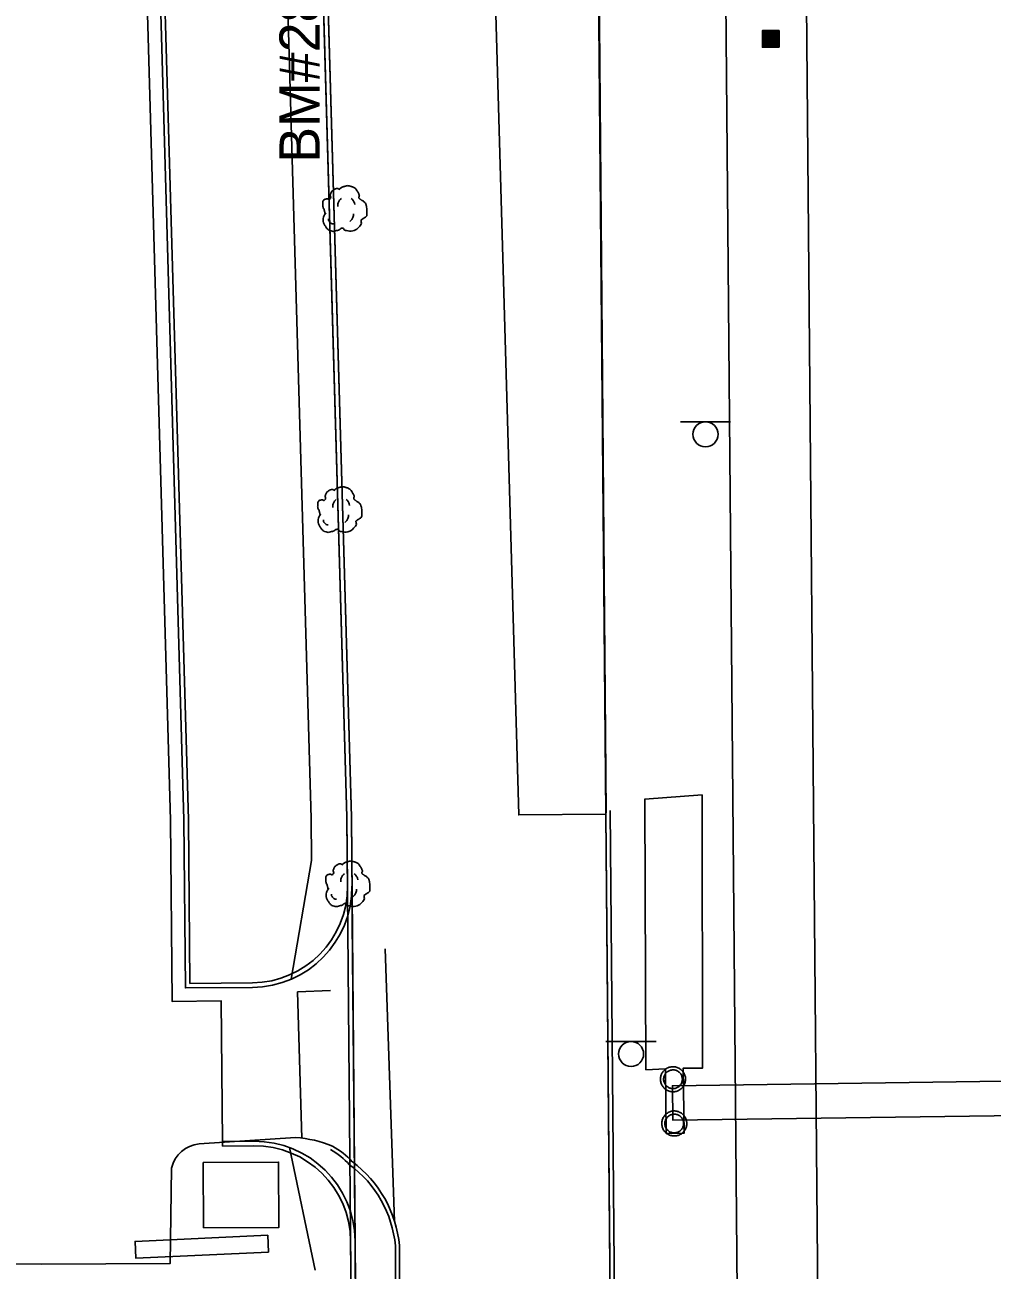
# Model space of a CAD drawing. Extents: x 2145380 to 2157287, y 139568 to 149130.
# Drawn here: x 2150661.9 to 2150806.3, y 141333.7 to 141519.7 of the extents above; entities that cross this region are included whole.
import ezdxf

# ---------------------------------------------------------------- set-up
doc = ezdxf.new("R2010")
doc.units = 0
for name, color, linetype in [('PR_PREVIOUSLY CONSTRUCTED', 7, 'Continuous'), ('SURV_Benchmark', 7, 'Continuous'), ('TOPO_Asphalt', 7, 'Continuous'), ('TOPO_Concrete', 7, 'Continuous'), ('TOPO_Curb Back', 7, 'Continuous'), ('TOPO_Misc', 7, 'Continuous'), ('TOPO_Power Pole', 7, 'Continuous'), ('TOPO_Sign', 7, 'Continuous'), ('TOPO_Tree', 7, 'Continuous'), ('TOPO_Wall Freestanding', 7, 'Continuous')]:
    doc.layers.add(name, color=color, linetype=linetype)

# ---------------------------------------------------------------- blocks, each defined once
blk = doc.blocks.new('CB')
at = {"layer": 'TOPO_Misc'}
for p, q in [((-3.08, 2.99), (3.24, 2.99)), ((-3.08, 2.68), (3.24, 2.68)), ((-3.08, 2.36), (3.24, 2.36)), ((-3.08, 2.05), (3.24, 2.05)), ((-3.08, 1.73), (3.24, 1.73)), ((-3.08, 1.4), (3.24, 1.4)), ((-3.08, 1.1), (3.24, 1.1)), ((-3.08, 0.77), (3.24, 0.77)), ((-3.08, 0.46), (3.24, 0.46)), ((-3.08, 0.14), (3.24, 0.14)), ((-3.08, -0.17), (3.24, -0.17)), ((-3.08, -0.48), (3.24, -0.48)), ((-3.08, -0.8), (3.24, -0.8)), ((-3.08, -1.11), (3.26, -1.11)), ((-3.08, -1.43), (3.26, -1.43)), ((-3.08, -1.75), (3.26, -1.75)), ((-3.08, -2.07), (3.26, -2.07)), ((-3.08, -2.39), (3.26, -2.39)), ((-3.08, -2.7), (3.26, -2.7)), ((-3.08, -3.02), (3.26, -3.02))]:
    blk.add_line(p, q, dxfattribs=at)
blk.add_lwpolyline([(3.26, -3.29), (3.24, 3.05), (-3.09, 3.04), (-3.08, -3.3), (3.26, -3.29)], dxfattribs=at)
blk = doc.blocks.new('TREE')
at = {"layer": 'TOPO_Tree'}
for points in [[(-3.49, 17.6), (-3.07, 18.27), (-2.58, 18.8), (-1.9, 19.19), (-1.05, 19.68), (-0.19, 19.96), (0.74, 20.24), (1.62, 20.51), (2.51, 20.82), (3.39, 20.77), (4.1, 20.73), (4.8, 20.47), (5.51, 20.24), (6.43, 19.95), (7.32, 19.73), (8.15, 19.19), (9.36, 18.4), (10.02, 17.21), (10.8, 16.01), (11.24, 15.33), (11.58, 14.62), (11.86, 13.89), (12.17, 13.08), (11.37, 12.02), (11.86, 11.25), (12, 11.03), (12.18, 10.86), (12.39, 10.72), (12.91, 10.35), (13.45, 10.02), (13.97, 9.66), (14.7, 9.16), (15.41, 8.68), (16.09, 8.07), (16.7, 7.53), (16.93, 6.73), (17.15, 5.95), (17.59, 4.38), (17.71, 2.77), (17.68, 1.19), (17.65, -0.25), (17.83, -2.22), (16.62, -3.04), (15.47, -3.83), (14.31, -4.58), (13.16, -5.35)], [(-14.07, -0.4), (-14.17, 0.5), (-14.37, 1.38), (-14.6, 2.25), (-14.84, 3.17), (-15.47, 3.96), (-15.66, 4.9), (-15.8, 5.59), (-15.71, 6.31), (-15.66, 7.01), (-15.6, 7.91), (-15.72, 8.8), (-15.13, 9.66), (-14.62, 10.42), (-13.76, 10.49), (-13.02, 10.72), (-12.18, 10.98), (-11.06, 10), (-10.37, 10.72), (-9.4, 11.74), (-10.29, 13.28), (-9.84, 14.42), (-9.56, 15.15), (-9.32, 15.89), (-8.78, 16.54), (-8.18, 17.26), (-7.5, 17.68), (-6.67, 18.13), (-6.14, 18.41), (-5.61, 18.61), (-5.08, 18.66), (-4.55, 18.71), (-4.02, 18.54), (-3.49, 18.13)], [(-4.21, 5.09), (-4.46, 6.09), (-4.3, 7.21), (-3.84, 8.21), (-3.33, 9.34), (-2.71, 10.27), (-1.64, 10.97)], [(5.89, 11.15), (6.5, 10.68), (6.96, 10.17), (7.36, 9.5), (7.93, 8.56), (8.31, 7.6), (8.46, 6.56)], [(13.16, -5.34), (13.25, -5.81), (13.36, -6.28), (13.45, -6.75), (13.76, -8.52), (12.24, -10.03), (10.8, -11.51), (9.98, -12.34), (9.13, -12.77), (8.15, -13.1), (5.97, -13.83), (3.32, -13.56), (1.27, -13.1), (0.49, -12.92), (-0.06, -11.44), (-0.84, -11.51), (-2.04, -11.61), (-3.28, -12.78), (-4.55, -13.1), (-6.06, -13.47), (-7.77, -14.03), (-9.31, -13.62), (-11.36, -13.09), (-12.84, -11.41), (-14.07, -9.39), (-15.32, -7.35), (-15.61, -5.13), (-15.13, -3.04), (-14.87, -1.89), (-13.91, -0.75), (-13.54, 0.13)], [(-11.38, -4.46), (-11.47, -5.41), (-11.03, -6.32), (-10.09, -7.22), (-9.3, -7.97), (-8.49, -8.26), (-7.7, -8.14)], [(4.79, -6.29), (5.71, -5.66), (6.3, -4.92), (6.81, -3.91), (7.36, -2.81), (7.63, -1.7), (7.54, -0.6)]]:
    blk.add_open_spline(points, degree=3, dxfattribs=at)

msp = doc.modelspace()

# ---------------------------------------------------------------- linework, layer by layer
at = {"layer": 'PR_PREVIOUSLY CONSTRUCTED'}
for p, q in [((2150710.64, 141401.31), (2150701.75, 141710.59)), ((2150704.64, 141401.14), (2150698.44, 141616.88)), ((2150709.98, 141401.3), (2150703.73, 141618.37)), ((2150704.7, 141394.85), (2150704.64, 141401.26)), ((2150710.06, 141391.02), (2150709.97, 141401.31)), ((2150712.62, 141175.71), (2150710.64, 141401.31)), ((2150750.61, 141176.04), (2150748.64, 141401.78)), ((2150701.67, 141377.12), (2150704.7, 141394.85)), ((2150685.86, 141375.81), (2150695.86, 141375.9)), ((2150686.52, 141376.48), (2150695.86, 141376.57)), ((2150683.88, 141373.79), (2150691.21, 141373.86)), ((2150691.4, 141352.86), (2150691.21, 141373.86)), ((2150691.4, 141352.86), (2150696.06, 141352.9)), ((2150691.4, 141352.86), (2150691.4, 141352.19)), ((2150691.4, 141352.19), (2150696.07, 141352.23)), ((2150701.41, 141351.97), (2150705.23, 141333.67)), ((2150711.09, 141273.77), (2150710.53, 141338.03))]:
    msp.add_line(p, q, dxfattribs=at)
for points in [[(2150764.84, 141722.12), (2150774.08, 140666.28)], [(2150776.84, 141722.22), (2150788.7, 140366.39)], [(2150746.27, 141672.29), (2150748.64, 141401.78)], [(2150680.41, 141606.01), (2150682.95, 141517.92), (2150686.31, 141400.93), (2150686.52, 141376.48)], [(2150679.77, 141605.33), (2150682.28, 141517.9), (2150685.64, 141400.92), (2150685.86, 141375.81)], [(2150677.82, 141603.31), (2150680.28, 141517.84), (2150683.64, 141400.88), (2150683.88, 141373.79)]]:
    msp.add_lwpolyline(points, dxfattribs=at)
for centre, radius, start, end in [((2150695.73, 141390.9), 15, 270.5015, 0.5015), ((2150695.73, 141390.9), 14.33, 270.5015, 0.5015), ((2150696.2, 141337.9), 15, 0.5015, 90.5015), ((2150696.2, 141337.9), 14.33, 0.5015, 90.5015)]:
    msp.add_arc(centre, radius, start, end, dxfattribs=at)
at = {"layer": 'TOPO_Asphalt'}
for p, q in [((2150717.09, 141340.93), (2150715.71, 141381.66)), ((2150707.51, 141375.44), (2150702.61, 141375.22)), ((2150703.25, 141353.37), (2150702.61, 141375.22))]:
    msp.add_line(p, q, dxfattribs=at)
for points in [[(2150687.92, 141352.52), (2150702.31, 141353.46)], [(2150507.36, 141335.36), (2150559.92, 141335.75), (2150664.35, 141334.54), (2150683.58, 141334.64), (2150683.79, 141348.9)]]:
    msp.add_lwpolyline(points, dxfattribs=at)
for centre, radius, start, end in [((2150701.16, 141335.83), 17.67, 67.7958, 86.2585), ((2150688.37, 141347.83), 4.71, 95.5163, 166.8365)]:
    msp.add_arc(centre, radius, start, end, dxfattribs=at)
at = {"layer": 'TOPO_Concrete'}
for points in [[(2150748.68, 141401.99), (2150746.33, 141679), (2150745.89, 141700.43)], [(2150645.26, 141604.93), (2150641.05, 141604.88), (2150641.07, 141602.89), (2150677.82, 141603.29), (2150680.28, 141517.84), (2150683.64, 141400.88), (2150683.88, 141373.79), (2150691.21, 141373.86), (2150691.4, 141352.86), (2150696.06, 141352.9)], [(2150695.86, 141375.9), (2150685.86, 141375.81), (2150685.64, 141400.92), (2150682.28, 141517.9), (2150679.77, 141605.32), (2150668.62, 141605.19)], [(2150754.48, 141404.03), (2150763.01, 141404.65), (2150763.06, 141363.82), (2150760.18, 141363.81), (2150760.32, 141354.11), (2150757.64, 141354.08), (2150757.54, 141363.74), (2150754.62, 141363.57)], [(2150711.2, 141338.03), (2150710.73, 141391.03)]]:
    msp.add_lwpolyline(points, dxfattribs=at)
for centre, start, end in [((2150695.73, 141390.9), 270.5015, 0.5015), ((2150696.2, 141337.9), 0.5015, 90.5015)]:
    msp.add_arc(centre, 15, start, end, dxfattribs=at)
at = {"layer": 'TOPO_Curb Back'}
for points in [[(2150712.62, 141175.71), (2150710.64, 141401.31), (2150701.75, 141710.59)], [(2150729.16, 141661.71), (2150728.16, 141661.69), (2150735.64, 141401.66), (2150748.64, 141401.78), (2150750.61, 141176.04)], [(2150711.95, 141175.71), (2150709.97, 141401.3), (2150703.7, 141619.51)], [(2150749.3, 141402.29), (2150751.28, 141176.05)], [(2150717.73, 141271.44), (2150717.35, 141302.24), (2150717.21, 141337.29)], [(2150718.33, 141271.46), (2150717.95, 141302.24), (2150717.81, 141337.32)]]:
    msp.add_lwpolyline(points, dxfattribs=at)
for centre, radius, start, end in [((2150701.61, 141341.33), 11.92, 42.624, 60.1597), ((2150701.61, 141341.33), 12.52, 42.8876, 60.1591), ((2150700.24, 141335.7), 17.05, 5.3752, 53.4905), ((2150700.24, 141335.7), 17.65, 5.2866, 53.3058)]:
    msp.add_arc(centre, radius, start, end, dxfattribs=at)
at = {"layer": 'TOPO_Power Pole'}
for points in [[(2150756.79, 141362.17), (2150756.8, 141362.3), (2150756.81, 141362.43), (2150756.83, 141362.56), (2150756.87, 141362.69), (2150756.91, 141362.82), (2150756.96, 141362.94), (2150757.02, 141363.06), (2150757.08, 141363.18), (2150757.17, 141363.28), (2150757.24, 141363.39), (2150757.33, 141363.48), (2150757.43, 141363.58), (2150757.53, 141363.66), (2150757.64, 141363.74), (2150757.76, 141363.81), (2150757.88, 141363.86), (2150757.99, 141363.92), (2150758.12, 141363.96), (2150758.25, 141364), (2150758.38, 141364.02), (2150758.51, 141364.04), (2150758.64, 141364.04), (2150758.77, 141364.04), (2150758.9, 141364.03), (2150759.03, 141364.01), (2150759.16, 141363.98), (2150759.29, 141363.94), (2150759.41, 141363.88), (2150759.53, 141363.83), (2150759.65, 141363.77), (2150759.76, 141363.7), (2150759.86, 141363.62), (2150759.96, 141363.53), (2150760.05, 141363.43), (2150760.14, 141363.33), (2150760.21, 141363.22), (2150760.28, 141363.11), (2150760.35, 141362.99), (2150760.4, 141362.87), (2150760.45, 141362.74), (2150760.48, 141362.62), (2150760.51, 141362.49), (2150760.53, 141362.36), (2150760.53, 141362.22), (2150760.53, 141362.1), (2150760.53, 141361.97), (2150760.5, 141361.83), (2150760.48, 141361.7), (2150760.44, 141361.58), (2150760.39, 141361.45), (2150760.33, 141361.34), (2150760.28, 141361.22), (2150760.2, 141361.11), (2150760.12, 141361), (2150760.03, 141360.9), (2150759.94, 141360.8), (2150759.84, 141360.72), (2150759.73, 141360.64), (2150759.63, 141360.57), (2150759.51, 141360.5), (2150759.39, 141360.45), (2150759.27, 141360.4), (2150759.13, 141360.36), (2150759.01, 141360.33), (2150758.88, 141360.31), (2150758.75, 141360.3), (2150758.62, 141360.3), (2150758.49, 141360.31), (2150758.36, 141360.33), (2150758.23, 141360.36), (2150758.1, 141360.39), (2150757.98, 141360.44), (2150757.85, 141360.49), (2150757.73, 141360.55), (2150757.63, 141360.62), (2150757.52, 141360.7), (2150757.41, 141360.78), (2150757.32, 141360.88), (2150757.23, 141360.97), (2150757.15, 141361.08), (2150757.08, 141361.19), (2150757.01, 141361.3), (2150756.95, 141361.43), (2150756.9, 141361.55), (2150756.86, 141361.68), (2150756.83, 141361.8), (2150756.81, 141361.93), (2150756.8, 141362.06), (2150756.79, 141362.17)], [(2150757.26, 141362.17), (2150757.27, 141362.28), (2150757.28, 141362.4), (2150757.3, 141362.51), (2150757.34, 141362.62), (2150757.38, 141362.73), (2150757.43, 141362.83), (2150757.49, 141362.93), (2150757.55, 141363.02), (2150757.63, 141363.11), (2150757.71, 141363.19), (2150757.79, 141363.27), (2150757.89, 141363.34), (2150757.98, 141363.39), (2150758.09, 141363.45), (2150758.19, 141363.49), (2150758.3, 141363.53), (2150758.42, 141363.55), (2150758.53, 141363.57), (2150758.64, 141363.57), (2150758.75, 141363.57), (2150758.86, 141363.56), (2150758.98, 141363.54), (2150759.09, 141363.51), (2150759.19, 141363.47), (2150759.3, 141363.43), (2150759.4, 141363.37), (2150759.49, 141363.3), (2150759.59, 141363.23), (2150759.67, 141363.15), (2150759.74, 141363.07), (2150759.82, 141362.97), (2150759.88, 141362.88), (2150759.93, 141362.77), (2150759.98, 141362.67), (2150760.01, 141362.56), (2150760.04, 141362.45), (2150760.06, 141362.33), (2150760.07, 141362.22), (2150760.07, 141362.11), (2150760.06, 141362), (2150760.03, 141361.89), (2150760.01, 141361.78), (2150759.97, 141361.67), (2150759.93, 141361.56), (2150759.88, 141361.46), (2150759.81, 141361.37), (2150759.74, 141361.27), (2150759.66, 141361.19), (2150759.58, 141361.11), (2150759.49, 141361.04), (2150759.39, 141360.98), (2150759.3, 141360.92), (2150759.18, 141360.87), (2150759.08, 141360.83), (2150758.97, 141360.8), (2150758.86, 141360.78), (2150758.74, 141360.77), (2150758.64, 141360.77), (2150758.52, 141360.78), (2150758.41, 141360.79), (2150758.29, 141360.82), (2150758.18, 141360.85), (2150758.08, 141360.9), (2150757.98, 141360.95), (2150757.88, 141361.02), (2150757.79, 141361.08), (2150757.7, 141361.15), (2150757.62, 141361.24), (2150757.54, 141361.33), (2150757.48, 141361.43), (2150757.43, 141361.52), (2150757.38, 141361.62), (2150757.33, 141361.73), (2150757.3, 141361.84), (2150757.28, 141361.95), (2150757.27, 141362.07), (2150757.26, 141362.17)], [(2150756.98, 141355.56), (2150756.99, 141355.7), (2150757, 141355.83), (2150757.03, 141355.95), (2150757.06, 141356.08), (2150757.1, 141356.21), (2150757.15, 141356.33), (2150757.21, 141356.45), (2150757.28, 141356.57), (2150757.36, 141356.68), (2150757.44, 141356.78), (2150757.52, 141356.88), (2150757.62, 141356.97), (2150757.72, 141357.05), (2150757.83, 141357.13), (2150757.95, 141357.2), (2150758.07, 141357.26), (2150758.18, 141357.31), (2150758.31, 141357.35), (2150758.44, 141357.39), (2150758.57, 141357.41), (2150758.7, 141357.43), (2150758.84, 141357.43), (2150758.96, 141357.43), (2150759.09, 141357.42), (2150759.22, 141357.4), (2150759.35, 141357.37), (2150759.48, 141357.33), (2150759.6, 141357.28), (2150759.72, 141357.23), (2150759.84, 141357.16), (2150759.95, 141357.09), (2150760.05, 141357.01), (2150760.15, 141356.92), (2150760.24, 141356.82), (2150760.33, 141356.72), (2150760.4, 141356.61), (2150760.48, 141356.5), (2150760.54, 141356.39), (2150760.59, 141356.26), (2150760.64, 141356.14), (2150760.67, 141356.01), (2150760.7, 141355.88), (2150760.72, 141355.75), (2150760.73, 141355.61), (2150760.73, 141355.49), (2150760.72, 141355.36), (2150760.7, 141355.23), (2150760.67, 141355.1), (2150760.63, 141354.97), (2150760.59, 141354.85), (2150760.53, 141354.73), (2150760.47, 141354.61), (2150760.4, 141354.5), (2150760.31, 141354.39), (2150760.23, 141354.29), (2150760.13, 141354.2), (2150760.04, 141354.11), (2150759.93, 141354.03), (2150759.82, 141353.96), (2150759.7, 141353.9), (2150759.58, 141353.84), (2150759.46, 141353.79), (2150759.33, 141353.76), (2150759.2, 141353.73), (2150759.07, 141353.71), (2150758.94, 141353.7), (2150758.81, 141353.7), (2150758.68, 141353.71), (2150758.55, 141353.72), (2150758.42, 141353.75), (2150758.3, 141353.78), (2150758.17, 141353.83), (2150758.05, 141353.88), (2150757.93, 141353.95), (2150757.82, 141354.01), (2150757.71, 141354.09), (2150757.6, 141354.17), (2150757.51, 141354.27), (2150757.42, 141354.36), (2150757.34, 141354.47), (2150757.27, 141354.58), (2150757.2, 141354.69), (2150757.15, 141354.82), (2150757.09, 141354.94), (2150757.05, 141355.07), (2150757.03, 141355.19), (2150757, 141355.32), (2150756.99, 141355.46), (2150756.98, 141355.56)], [(2150757.45, 141355.56), (2150757.46, 141355.67), (2150757.47, 141355.79), (2150757.5, 141355.9), (2150757.53, 141356.01), (2150757.57, 141356.12), (2150757.62, 141356.22), (2150757.68, 141356.32), (2150757.75, 141356.41), (2150757.82, 141356.5), (2150757.9, 141356.58), (2150757.99, 141356.66), (2150758.08, 141356.73), (2150758.18, 141356.79), (2150758.28, 141356.84), (2150758.38, 141356.88), (2150758.49, 141356.92), (2150758.61, 141356.94), (2150758.72, 141356.96), (2150758.84, 141356.96), (2150758.95, 141356.96), (2150759.05, 141356.96), (2150759.17, 141356.93), (2150759.28, 141356.9), (2150759.39, 141356.86), (2150759.5, 141356.82), (2150759.59, 141356.76), (2150759.69, 141356.69), (2150759.78, 141356.62), (2150759.86, 141356.55), (2150759.94, 141356.46), (2150760.01, 141356.36), (2150760.07, 141356.27), (2150760.12, 141356.16), (2150760.17, 141356.06), (2150760.2, 141355.95), (2150760.24, 141355.84), (2150760.25, 141355.73), (2150760.26, 141355.61), (2150760.26, 141355.51), (2150760.25, 141355.4), (2150760.23, 141355.28), (2150760.2, 141355.17), (2150760.16, 141355.06), (2150760.12, 141354.96), (2150760.07, 141354.86), (2150760, 141354.76), (2150759.94, 141354.66), (2150759.85, 141354.58), (2150759.77, 141354.5), (2150759.68, 141354.43), (2150759.58, 141354.37), (2150759.49, 141354.31), (2150759.38, 141354.26), (2150759.28, 141354.22), (2150759.16, 141354.2), (2150759.05, 141354.17), (2150758.93, 141354.16), (2150758.83, 141354.16), (2150758.71, 141354.17), (2150758.6, 141354.19), (2150758.48, 141354.21), (2150758.37, 141354.25), (2150758.27, 141354.29), (2150758.17, 141354.34), (2150758.07, 141354.41), (2150757.98, 141354.47), (2150757.89, 141354.55), (2150757.81, 141354.63), (2150757.74, 141354.72), (2150757.67, 141354.82), (2150757.62, 141354.91), (2150757.57, 141355.01), (2150757.52, 141355.12), (2150757.5, 141355.24), (2150757.47, 141355.35), (2150757.46, 141355.46), (2150757.45, 141355.56)]]:
    msp.add_lwpolyline(points, dxfattribs=at)
at = {"layer": 'TOPO_Sign'}
for points in [[(2150759.77, 141460.37), (2150767.27, 141460.37)], [(2150763.52, 141460.37), (2150763.52, 141460.37)], [(2150761.66, 141458.5), (2150761.66, 141458.5)], [(2150765.39, 141458.5), (2150765.39, 141458.5)], [(2150763.52, 141456.63), (2150763.52, 141456.63)], [(2150748.66, 141367.81), (2150756.15, 141367.82)], [(2150752.41, 141367.81), (2150752.41, 141367.81)], [(2150750.54, 141365.95), (2150750.54, 141365.95)], [(2150754.28, 141365.95), (2150754.28, 141365.95)], [(2150752.41, 141364.08), (2150752.41, 141364.08)]]:
    msp.add_lwpolyline(points, dxfattribs=at)
for points in [[(2150839.83, 141362.32), (2150758.58, 141361.21), (2150758.65, 141356.05), (2150839.9, 141357.16)], [(2150698.27, 141336.34), (2150678.46, 141335.44), (2150678.35, 141337.95), (2150698.16, 141338.86)]]:
    msp.add_lwpolyline(points, close=True, dxfattribs=at)
for centre, start, end in [((2150763.52, 141458.5), 90, 180), ((2150763.52, 141458.5), 360, 90), ((2150763.52, 141458.5), 180, 270), ((2150763.52, 141458.5), 270, 0), ((2150752.41, 141365.95), 90, 180), ((2150752.41, 141365.95), 360, 90), ((2150752.41, 141365.95), 180, 270), ((2150752.41, 141365.95), 270, 0)]:
    msp.add_arc(centre, 1.87, start, end, dxfattribs=at)
at = {"layer": 'TOPO_Wall Freestanding'}
msp.add_line((2150754.48, 141404.04), (2150754.62, 141363.57), dxfattribs=at)
msp.add_lwpolyline([(2150688.57, 141339.98), (2150688.52, 141349.73), (2150699.78, 141349.79), (2150699.83, 141340.04)], close=True, dxfattribs=at)

# ---------------------------------------------------------------- block references
at = {"layer": 'TOPO_Misc', "xscale": 0.39370000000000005, "yscale": 0.3937000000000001}
msp.add_blockref('CB', (2150773.23, 141517.61), dxfattribs=at)
at = {"layer": 'TOPO_Tree', "xscale": 0.19685000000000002, "yscale": 0.19685000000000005}
for p in [(2150709.47, 141491.55), (2150708.71, 141446.59), (2150709.92, 141390.68)]:
    msp.add_blockref('TREE', p, dxfattribs=at)

# ---------------------------------------------------------------- texts
at = {"layer": 'SURV_Benchmark'}
msp.add_text('BM#28', height=6, rotation=90, dxfattribs=at).set_placement((2150705.9, 141499.06))

doc.saveas('drawing.dxf')
